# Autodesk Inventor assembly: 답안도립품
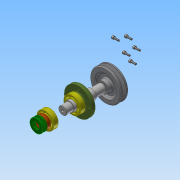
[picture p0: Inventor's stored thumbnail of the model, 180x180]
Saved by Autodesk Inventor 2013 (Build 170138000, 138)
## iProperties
Created: 2016-06
Part Number: 답안도립품
Document SubType Name: Assembly
Designer: Administrator
Author: Administrator
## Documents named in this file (12)
- C:\Users\Administrator\Desktop\460607V1014\답안도립품.iam
- C:\Users\Administrator\Desktop\460607V1014\1-본체.ipt
- C:\Users\Administrator\Desktop\460607V1014\커버.ipt
- C:\Users\Administrator\Desktop\460607V1014\축.ipt
- C:\Users\Administrator\Desktop\460607V1014\베어링 6004.ipt
- C:\Users\Administrator\Desktop\460607V1014\어댑터슬리브.ipt
- C:\Users\Administrator\Desktop\460607V1014\베어링 51202.ipt
- C:\Users\Administrator\Desktop\460607V1014\오일 실.ipt
- C:\Users\Administrator\Desktop\460607V1014\키 5 x 5 x 16.ipt
- C:\Users\Administrator\Desktop\460607V1014\V벨트풀리.ipt
- C:\Users\Administrator\Desktop\460607V1014\멈춤나사 M3x8.ipt
- C:\Users\Administrator\Desktop\460607V1014\볼트 M4 x 12.ipt
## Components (7 placed, 3 different names)
1. 1-본체:1
2. V벨트풀리:1 — 각도:2
3. ISO 4762 M4 x 12:1
4. ISO 4762 M4 x 12:2
5. ISO 4762 M4 x 12:3
6. ISO 4762 M4 x 12:4
7. ISO 4762 M4 x 12:5
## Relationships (1: Angle 1)
- 각도:2 [Angle]: V벨트풀리:1
